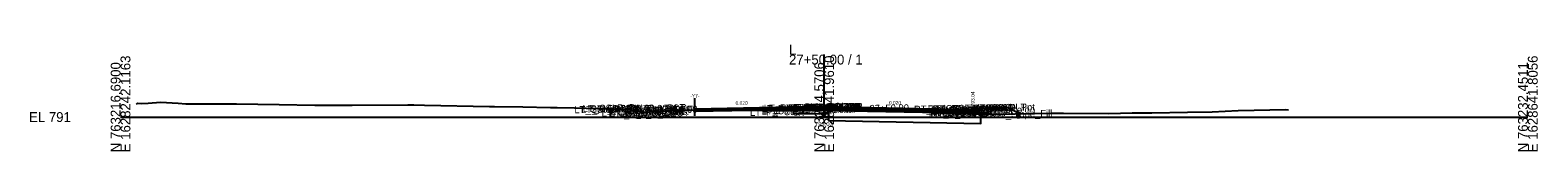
# Model space of a CAD drawing. Extents: x -26 to 4403, y -510 to 9556.
# Drawn here: x 974.3 to 1402.8, y 7490.3 to 7520.5 of the extents above; entities that cross this region are included whole.
import ezdxf

# ---------------------------------------------------------------- set-up
doc = ezdxf.new("R2010")
doc.units = 0
for name, color, linetype in [('Default', 7, 'Continuous'), ('Exist CMT Pavement', 7, 'Continuous'), ('Exist Cross Section Cell', 7, 'Continuous'), ('Exist XS Center Line Elevation Label', 7, 'Continuous'), ('Exist XS Ground Line', 7, 'Continuous'), ('Prop CMT Conc Surface', 7, 'Continuous'), ('Prop CMT Concrete Structures', 7, 'Continuous'), ('Prop CMT Pvmt Course 1', 7, 'Continuous'), ('Prop CMT Pvmt Course 1 CG', 7, 'Continuous'), ('Prop CMT Pvmt Course 2', 7, 'Continuous'), ('Prop CMT Pvmt Course 3', 7, 'Continuous'), ('Prop CMT Pvmt Surface', 7, 'Continuous'), ('Prop CMT Pvmt Wedge Surface 1', 7, 'Continuous'), ('Prop CMT Pvmt Wedge Surface 2', 7, 'Continuous'), ('Prop CMT Pvmt Wedge Surface 3', 7, 'Continuous'), ('Prop CMT Shallow Undercut', 7, 'Continuous'), ('Prop CMT Shallow Undercut Boundary', 7, 'Continuous'), ('Prop CMT Shear Line', 7, 'Continuous'), ('Prop CMT Slope Grass', 7, 'Continuous'), ('Prop CMT Subgrade Earthwork', 7, 'Continuous'), ('Prop CMT Undercut Boundary', 7, 'Continuous'), ('Prop XS Finish Grade CurbGutter', 7, 'Continuous'), ('Prop XS Hydro Elevations', 7, 'Continuous'), ('Prop XS SE Text', 7, 'Continuous'), ('Prop XS Side Slope Text', 7, 'Continuous'), ('Scratch_Level_0', 7, 'Continuous')]:
    doc.layers.add(name, color=color, linetype=linetype)

msp = doc.modelspace()

# ---------------------------------------------------------------- linework, layer by layer
at = {"layer": 'Exist CMT Pavement'}
msp.add_lwpolyline([(1163.25, 7502.09), (1171.31, 7502.21), (1178.52, 7501.99), (1191.24, 7501.78)], dxfattribs=at)
at = {"layer": 'Exist Cross Section Cell'}
for p, q in [((1200, 7500), (1200, 7517.74)), ((1000, 7500), (1200, 7500)), ((1200, 7500), (1400, 7500))]:
    msp.add_line(p, q, dxfattribs=at)
at = {"layer": 'Exist XS Ground Line'}
msp.add_lwpolyline([(1004.51, 7503.71), (1004.86, 7503.94), (1005.95, 7503.88), (1007.82, 7503.98), (1011.37, 7504.26), (1016.38, 7503.95), (1018.51, 7503.79), (1019.82, 7503.78), (1032.96, 7503.78), (1045.08, 7503.59), (1055.23, 7503.37), (1062.87, 7503.42), (1065.81, 7503.39), (1081.62, 7503.48), (1082.96, 7503.48), (1083.33, 7503.47), (1086.4, 7503.42), (1104.83, 7503.05), (1106.26, 7503.02), (1114.38, 7502.91), (1122.17, 7502.72), (1123.42, 7502.69), (1124.12, 7502.7), (1128.99, 7502.62), (1142.43, 7502.25), (1145.21, 7502.04), (1146.04, 7501.96), (1148.1, 7501.7), (1148.64, 7501.41), (1154.69, 7501.74), (1163.42, 7502.1), (1171.31, 7502.21), (1178.52, 7501.99), (1191.24, 7501.78), (1192.33, 7501.58), (1192.56, 7501.9), (1192.81, 7501.85), (1193.21, 7501.98), (1195.23, 7502.12), (1196.81, 7502.13), (1200, 7502.03), (1203.72, 7501.91), (1204.48, 7501.9), (1212.26, 7501.67), (1227.93, 7501.44), (1228.29, 7501.44), (1231.77, 7501.3), (1242.65, 7500.92), (1247.75, 7500.81), (1249, 7500.79), (1264.52, 7501.08), (1268.04, 7501.15), (1280.86, 7500.97), (1287.57, 7501.21), (1293.11, 7501.22), (1303.27, 7501.35), (1310.26, 7501.51), (1317.69, 7501.84), (1331.17, 7502.11), (1331.93, 7502.09)], dxfattribs=at)
at = {"layer": 'Prop CMT Conc Surface'}
for points in [[(1240.22, 7502.16), (1242.22, 7502.04)], [(1242.22, 7502.04), (1242.22, 7502.54), (1242.72, 7502.54)], [(1246.72, 7502.63), (1251.72, 7502.73)]]:
    msp.add_lwpolyline(points, dxfattribs=at)
at = {"layer": 'Prop CMT Concrete Structures'}
for points in [[(1240.22, 7502.16), (1242.22, 7502.04), (1242.22, 7502.54), (1242.72, 7502.54)], [(1242.72, 7502.54), (1242.72, 7501.53), (1240.22, 7501.58)], [(1240.22, 7501.58), (1240.22, 7502.16)], [(1251.72, 7502.73), (1246.72, 7502.63)], [(1246.72, 7502.63), (1246.72, 7502.3)], [(1246.72, 7502.3), (1251.72, 7502.4)], [(1251.72, 7502.4), (1251.72, 7502.73)]]:
    msp.add_lwpolyline(points, dxfattribs=at)
at = {"layer": 'Prop CMT Pvmt Course 1'}
for points in [[(1200, 7502.97), (1163.25, 7502.23)], [(1163.25, 7501.98), (1200, 7502.72)], [(1200, 7502.84), (1192.33, 7502.69)], [(1192.33, 7502.56), (1200, 7502.72)], [(1192.33, 7502.69), (1192.33, 7502.56)], [(1200, 7502.72), (1200, 7502.97)], [(1200, 7502.97), (1240.22, 7502.16)], [(1200, 7502.72), (1200, 7502.97)], [(1200, 7502.72), (1200, 7502.84)], [(1240.22, 7501.91), (1200, 7502.72)], [(1240.22, 7502.16), (1240.22, 7501.91)]]:
    msp.add_lwpolyline(points, dxfattribs=at)
msp.add_lwpolyline([(1200, 7502.72), (1200, 7502.84), (1200, 7502.84), (1200, 7502.72)], close=True, dxfattribs=at)
at = {"layer": 'Prop CMT Pvmt Course 1 CG'}
for points in [[(1240.22, 7501.58), (1243.22, 7501.52), (1243.56, 7501.18)], [(1240.22, 7501.25), (1240.22, 7501.58)], [(1243.56, 7501.18), (1240.22, 7501.25)]]:
    msp.add_lwpolyline(points, dxfattribs=at)
at = {"layer": 'Prop CMT Pvmt Course 2'}
for points in [[(1200, 7502.72), (1163.25, 7501.98)], [(1163.25, 7501.65), (1200, 7502.38)], [(1200, 7502.72), (1192.33, 7502.56)], [(1192.33, 7502.56), (1192.33, 7502.23)], [(1192.33, 7502.23), (1200, 7502.38)], [(1200, 7502.38), (1200, 7502.72)], [(1200, 7502.38), (1200, 7502.72)], [(1200, 7502.38), (1200, 7502.72)], [(1200, 7502.72), (1240.22, 7501.91)], [(1240.22, 7501.58), (1200, 7502.38)], [(1240.22, 7501.91), (1240.22, 7501.58)]]:
    msp.add_lwpolyline(points, dxfattribs=at)
at = {"layer": 'Prop CMT Pvmt Course 3'}
for points in [[(1200, 7502.38), (1163.25, 7501.65)], [(1191.24, 7501.88), (1200, 7502.05)], [(1200, 7502.38), (1192.33, 7502.23)], [(1192.33, 7502.23), (1192.33, 7501.9)], [(1192.33, 7501.9), (1200, 7502.05)], [(1200, 7502.05), (1200, 7502.38)], [(1200, 7502.05), (1200, 7502.38)], [(1200, 7502.38), (1240.22, 7501.58)], [(1200, 7502.05), (1200, 7502.38)], [(1240.22, 7501.25), (1200, 7502.05)], [(1240.22, 7501.58), (1240.22, 7501.25)]]:
    msp.add_lwpolyline(points, dxfattribs=at)
at = {"layer": 'Prop CMT Pvmt Surface'}
for points in [[(1200, 7502.97), (1163.25, 7502.23)], [(1200, 7502.97), (1240.22, 7502.16)]]:
    msp.add_lwpolyline(points, dxfattribs=at)
at = {"layer": 'Prop CMT Pvmt Wedge Surface 1'}
for points in [[(1200, 7502.72), (1192.33, 7502.56)], [(1192.33, 7502.56), (1192.33, 7502.69)], [(1200, 7502.97), (1200, 7502.72)]]:
    msp.add_lwpolyline(points, dxfattribs=at)
at = {"layer": 'Prop CMT Pvmt Wedge Surface 2'}
for points in [[(1200, 7502.72), (1192.33, 7502.56)], [(1200, 7502.97), (1200, 7502.72)]]:
    msp.add_lwpolyline(points, dxfattribs=at)
at = {"layer": 'Prop CMT Pvmt Wedge Surface 3'}
for points in [[(1200, 7502.38), (1192.33, 7502.23)], [(1200, 7502.97), (1200, 7502.38)]]:
    msp.add_lwpolyline(points, dxfattribs=at)
at = {"layer": 'Prop CMT Shallow Undercut'}
msp.add_lwpolyline([(1191.24, 7500.88), (1200, 7501.05), (1201.24, 7501.03), (1201.24, 7501.99), (1200, 7502.03), (1199.64, 7502.04), (1193, 7501.91), (1192.81, 7501.85), (1192.56, 7501.9), (1192.33, 7501.58), (1191.24, 7501.78)], close=True, dxfattribs=at)
at = {"layer": 'Prop CMT Shallow Undercut Boundary'}
msp.add_lwpolyline([(1191.24, 7501.78), (1191.24, 7500.88), (1200, 7501.05), (1201.24, 7501.03), (1201.24, 7501.99), (1199.64, 7502.04), (1193, 7501.91), (1192.81, 7501.85), (1192.56, 7501.9), (1192.33, 7501.58)], close=True, dxfattribs=at)
at = {"layer": 'Prop CMT Shear Line'}
msp.add_line((1163.25, 7500.36), (1163.25, 7505.4), dxfattribs=at)
at = {"layer": 'Prop CMT Slope Grass'}
for p, q in [((1242.72, 7502.54), (1252.22, 7502.73)), ((1252.22, 7502.73), (1254.88, 7501.4))]:
    msp.add_line(p, q, dxfattribs=at)
msp.add_lwpolyline([(1254.88, 7501.4), (1254.88, 7499.91), (1255.55, 7499.91), (1255.55, 7500.9)], dxfattribs=at)
at = {"layer": 'Prop CMT Subgrade Earthwork'}
msp.add_line((1191.24, 7501.88), (1191.24, 7501.78), dxfattribs=at)
for points in [[(1200, 7502.05), (1191.24, 7501.88)], [(1200, 7502.05), (1240.22, 7501.25)], [(1240.22, 7501.25), (1243.56, 7501.18), (1244.97, 7502.59)]]:
    msp.add_lwpolyline(points, dxfattribs=at)
at = {"layer": 'Prop CMT Undercut Boundary'}
msp.add_lwpolyline([(1201.24, 7501.99), (1201.24, 7499.02), (1201.24, 7499.02), (1244.56, 7498.16), (1244.56, 7500.88), (1242.03, 7500.94), (1240.66, 7500.99), (1237, 7501.12), (1235.47, 7501.17), (1234.07, 7501.22), (1233.29, 7501.25), (1228.29, 7501.44), (1228.12, 7501.44), (1226.17, 7501.47), (1220.73, 7501.55), (1216.87, 7501.6), (1216.77, 7501.6), (1216.73, 7501.6), (1216.02, 7501.62), (1215.07, 7501.63), (1214.47, 7501.64), (1213.52, 7501.65), (1212.7, 7501.66), (1211.83, 7501.68), (1208.21, 7501.79), (1204.48, 7501.9), (1203.72, 7501.91)], close=True, dxfattribs=at)
at = {"layer": 'Prop XS Finish Grade CurbGutter'}
for p, q in [((1254.88, 7501.4), (1255.07, 7501.4)), ((1254.88, 7501.4), (1255.55, 7501.4)), ((1254.88, 7501.4), (1254.88, 7500.41)), ((1254.88, 7500.41), (1254.88, 7499.91)), ((1254.88, 7500.41), (1255.55, 7500.41)), ((1254.88, 7499.91), (1255.55, 7499.91)), ((1255.55, 7500.99), (1255.19, 7501.35)), ((1255.55, 7500.99), (1255.55, 7500.41)), ((1255.55, 7500.9), (1255.55, 7500.9)), ((1255.55, 7500.41), (1255.55, 7499.91))]:
    msp.add_line(p, q, dxfattribs=at)
msp.add_arc((1255.07, 7501.24), 0.166, 43.9997, 90, dxfattribs=at)

# ---------------------------------------------------------------- texts
at = {"layer": 'Default'}
msp.add_text('-', height=0.0001, dxfattribs=at).set_placement((1000, 7500))
at = {"layer": 'Exist Cross Section Cell'}
for s, p in [('E 1628242.1163', (1002.8, 7490)), ('E 1628441.9610', (1202.8, 7490)), ('E 1628641.8056', (1402.8, 7490)), ('N 763216.6900', (1000, 7490)), ('N 763224.5706', (1200, 7490)), ('N 763232.4511', (1400, 7490))]:
    msp.add_text(s, height=2.8, rotation=90, dxfattribs=at).set_placement(p)
for s, p in [('27+50.00 / 1', (1190, 7514.94)), ('L', (1190, 7517.74)), ('EL 791', (974, 7498.6))]:
    msp.add_text(s, height=2.8, dxfattribs=at).set_placement(p)
at = {"layer": 'Exist XS Center Line Elevation Label'}
msp.add_text('793.03', height=1.2, dxfattribs=at).set_placement((1197.39, 7497.43))
at = {"layer": 'Prop XS Hydro Elevations'}
for s, rotation, p in [('-Y7-', 360, (1161.95, 7505.55)), ('793.04', 90, (1242.72, 7503.04))]:
    msp.add_text(s, height=1, rotation=rotation, dxfattribs=at).set_placement(p)
at = {"layer": 'Prop XS SE Text'}
for rotation, p in [(1.1467, (1174.82, 7503.46)), (358.8535, (1218.38, 7503.6))]:
    msp.add_text('0.020', height=1, rotation=rotation, dxfattribs=at).set_placement(p)
at = {"layer": 'Prop XS Side Slope Text'}
msp.add_text('2:1', height=1, rotation=333.4349, dxfattribs=at).set_placement((1252.56, 7502.75))
at = {"layer": 'Scratch_Level_0'}
for s, p in [('LT_Sub_Trench_Out_DLT', (1129.03, 7501.07)), ('LT_CSLP_Pnt', (1131.38, 7501.4)), ('LT_CG_Top_BOC', (1138.99, 7501.18)), ('LT_PV2_IEEOP', (1182.3, 7501.36)), ('LT_PV1_IEEOP', (1182.87, 7501.5)), ('RT_PV2_OEEOP', (1189.28, 7501.5)), ('LT_PV2_OEEOP', (1189.33, 7501.5)), ('RT_PV1_OEEOP', (1189.85, 7501.64)), ('LT_PV1_OEEOP', (1189.9, 7501.64)), ('RT_PV2_IEEOP', (1189.93, 7501.52)), ('RT_PV1_IEEOP', (1190.49, 7501.65)), ('PV2_PGL', (1193.93, 7501.6)), ('PV1_PGL', (1194.49, 7501.86)), ('27+50.00', (1212.89, 7501.44)), ('RT_Sub_Trench_Out_DLT', (1225.52, 7501.2)), ('RT_CG_Top_Face', (1229.46, 7501.29)), ('RT_CG_Top_BOC', (1230.98, 7501.31)), ('27+50.00', (1236.02, 7501.41)), ('RT_CSLP_Pnt', (1242.37, 7501.54)), ('27+50.00', (1242.46, 7501.54)), ('LT_Slope_Fill', (1130.86, 7501.12)), ('27+50.00', (1133.89, 7501.28)), ('LT_CG1_Shelf_Out', (1136.76, 7500.12)), ('LT_CG_Top_Face', (1138.47, 7501.16)), ('LT_CG_Bot_BOC', (1139.03, 7500.16)), ('LT_CG_Top_Gut', (1139.45, 7500.68)), ('LT_Sub_OEOP', (1139.98, 7499.85)), ('27+50.00', (1140.56, 7501.34)), ('LT_CG_Bot_IE', (1143.12, 7500.25)), ('LT_Sub_OEOT', (1143.29, 7499.92)), ('LT_PV2_OEOT', (1143.38, 7500.58)), ('LT_PV3_OEOT', (1143.38, 7500.25)), ('LT_PV1_OEOT', (1143.95, 7500.85)), ('27+50.00', (1144.28, 7501.28)), ('27+50.00', (1152.78, 7501.02)), ('LT_PV_Sub_Tie_In', (1178.9, 7500.32)), ('LT_Sub_IEEOP', (1182.21, 7500.7)), ('LT_PV3_IEEOP', (1182.3, 7501.03)), ('RT_Sub_OEEOP', (1189.19, 7500.83)), ('LT_Sub_OEEOP', (1189.23, 7500.84)), ('RT_PV3_OEEOP', (1189.28, 7501.17)), ('LT_PV3_OEEOP', (1189.33, 7501.17)), ('Sub_PGL', (1193.83, 7500.93)), ('PV3_PGL', (1193.93, 7501.26)), ('RT_CG1_Shelf_Out', (1229.75, 7500.25)), ('RT_CG_Bot_IE', (1230.11, 7500.38)), ('RT_Sub_OEOT', (1230.28, 7500.05)), ('RT_PV2_OEOT', (1230.37, 7500.72)), ('RT_PV3_OEOT', (1230.37, 7500.38)), ('RT_CG_Top_Gut', (1230.43, 7500.81)), ('RT_PV1_OEOT', (1230.94, 7500.98)), ('RT_CG_Bot_BOC', (1231.01, 7500.3)), ('RT_Sub_OEOP', (1233.65, 7499.98)), ('RT_Slope_Fill', (1248.06, 7499.76)), ('27+50.00', (1248.73, 7500.52))]:
    msp.add_text(s, height=2, rotation=1.1458, dxfattribs=at).set_placement(p)

doc.saveas('drawing.dxf')
